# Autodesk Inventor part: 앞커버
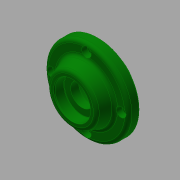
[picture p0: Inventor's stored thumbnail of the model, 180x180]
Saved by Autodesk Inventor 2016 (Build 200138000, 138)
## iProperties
Created: 2017-08
Part Number: 앞커버
Material: 알루미늄 6061
Document SubType Name: Modeling
Designer: mduedu
Density: 1 g/cm^3
Appearance: 진녹색
Author: mduedu
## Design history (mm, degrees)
sketch "스케치1"
  geometry: C1 r 35 at (0, 0); 1 further point
  constraints: 1 centre point, 1 coincident
  dimensions: "d0" = 70 diameter of C1
extrude "돌출1" new body sketch "스케치1" distance "d1" = 10; taper "d2" = 0 deg
sketch "스케치2"
  geometry: C1 r 24 at (0, 0); 1 further point
  constraints: 1 centre point, 1 coincident
  dimensions: "d3" = 48 diameter of C1
node "작업 평면1"
sketch "스케치3"
  geometry: C1 r 20 at (0, 0); 1 further point
  constraints: 1 centre point, 1 coincident
  dimensions: "d5" = 40 diameter of C1
feature "로프트1" sketch "스케치3" dims "d6" = 0, "d7" = 90 deg, "d8" = 0, "d9" = 90 deg
sketch "스케치4"
  geometry: C1 r 24 at (0, 0) reference; 1 further point
extrude "돌출2" join sketch "스케치4" distance "d10" = 8; taper "d11" = 0 deg
hole "구멍1" diameter "d14" = 40; stored, may be unused: countersink angle "d18" = 90 deg, drill point angle "d20" = 0 deg; dims "d12" = 10, "d13" = 10, "d15" = 6, "d16" = 4, "d17" = 2, "d19" = 12
hole "구멍2" diameter "d23" = 34; stored, may be unused: countersink angle "d27" = 90 deg, drill point angle "d29" = 0 deg; dims "d21" = 10, "d22" = 10, "d24" = 6, "d25" = 4, "d26" = 2, "d28" = 3
hole "구멍3" diameter "d32" = 19; stored, may be unused: countersink angle "d36" = 90 deg, drill point angle "d38" = 0 deg; dims "d30" = 10, "d31" = 10, "d33" = 6, "d34" = 4, "d35" = 2, "d37" = 3
chamfer "모따기1" distance "d39" = 1; stored, may be unused: second distance "d40" = 2, angle "d41" = 45 deg
sketch "스케치5"
  geometry: C1 r 15 at (0, 0); 1 further point
  constraints: 1 centre point, 1 coincident
  dimensions: "d42" = 30 diameter of C1
extrude "돌출3" cut sketch "스케치5" distance "d43" = 8.3; taper "d44" = 0 deg
chamfer "모따기2" distance "d47" = 0.8; stored, may be unused: second distance "d48" = 2, angle "d49" = 30 deg
fillet "모깎기1" dims "d50" = 0.3
fillet "모깎기2" dims "d51" = 0.3
fillet "모깎기3" dims "d52" = 3
sketch "스케치6" dims "d53" = 58
  geometry: 6 further points
  constraints: 2 vertical alignment, 1 coincident, 7 other
  dimensions: "d56" = 360 deg dimension on point (0, 0) point (0, 29) (derived)
sketch "스케치9"
  geometry: 4 further points
  constraints: 4 other
hole "구멍6" sketch "스케치9" at (-29, 0), (0, -29), (29, 0), (0, 29) diameter "d72" = 4.5; stored, may be unused: countersink angle "d76" = 90 deg, drill point angle "d78" = 0 deg; dims "d73" = 6, "d74" = 8, "d75" = 4.6, "d77" = 8
fillet "모깎기4" dims "d79" = 3
fillet "모깎기5" dims "d80" = 3
fillet "모깎기6" dims "d81" = 3
chamfer "모따기3" distance "d82" = 1; stored, may be unused: second distance "d83" = 2, angle "d84" = 30 deg
node "솔리드1"
other parameters: "d4" = 12
